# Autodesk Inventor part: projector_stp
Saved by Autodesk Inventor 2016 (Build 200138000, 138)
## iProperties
Created: 2016-01
Part Number: projector_stp
Material: Generic
Document SubType Name: Modeling
Designer: John
Density: 1 g/cm^3
Appearance: Default
Author: John
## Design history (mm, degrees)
feature "SOLID33"
feature "SOLID31"
feature "SOLID29"
feature "SOLID27"
feature "SOLID25"
feature "SOLID22"
feature "SOLID19"
feature "SOLID18"
feature "SOLID5:1"
feature "SOLID15"
feature "SOLID3:1"
feature "SOLID2:1"
feature "SOLID6:1"
feature "SOLID10:1"
feature "SOLID9:1"
feature "SOLID7:1"
feature "SOLID14:1"
feature "SOLID11:1"
feature "SOLID71"
feature "SOLID69"
feature "SOLID41"
feature "SOLID37"
feature "SOLID35"
body "Solid1"
body "Solid2"
body "Solid3"
body "Solid4"
body "Solid5"
body "Solid6"
body "Solid7"
body "Solid8"
body "Solid9"
body "Solid10"
body "Solid11"
body "Solid12"
body "Solid13"
body "Solid14"
body "Solid15"
body "Solid16"
body "Solid17"
body "Solid18"
body "Solid19"
body "Solid20"
body "Solid21"
body "Solid22"
body "Solid23"
